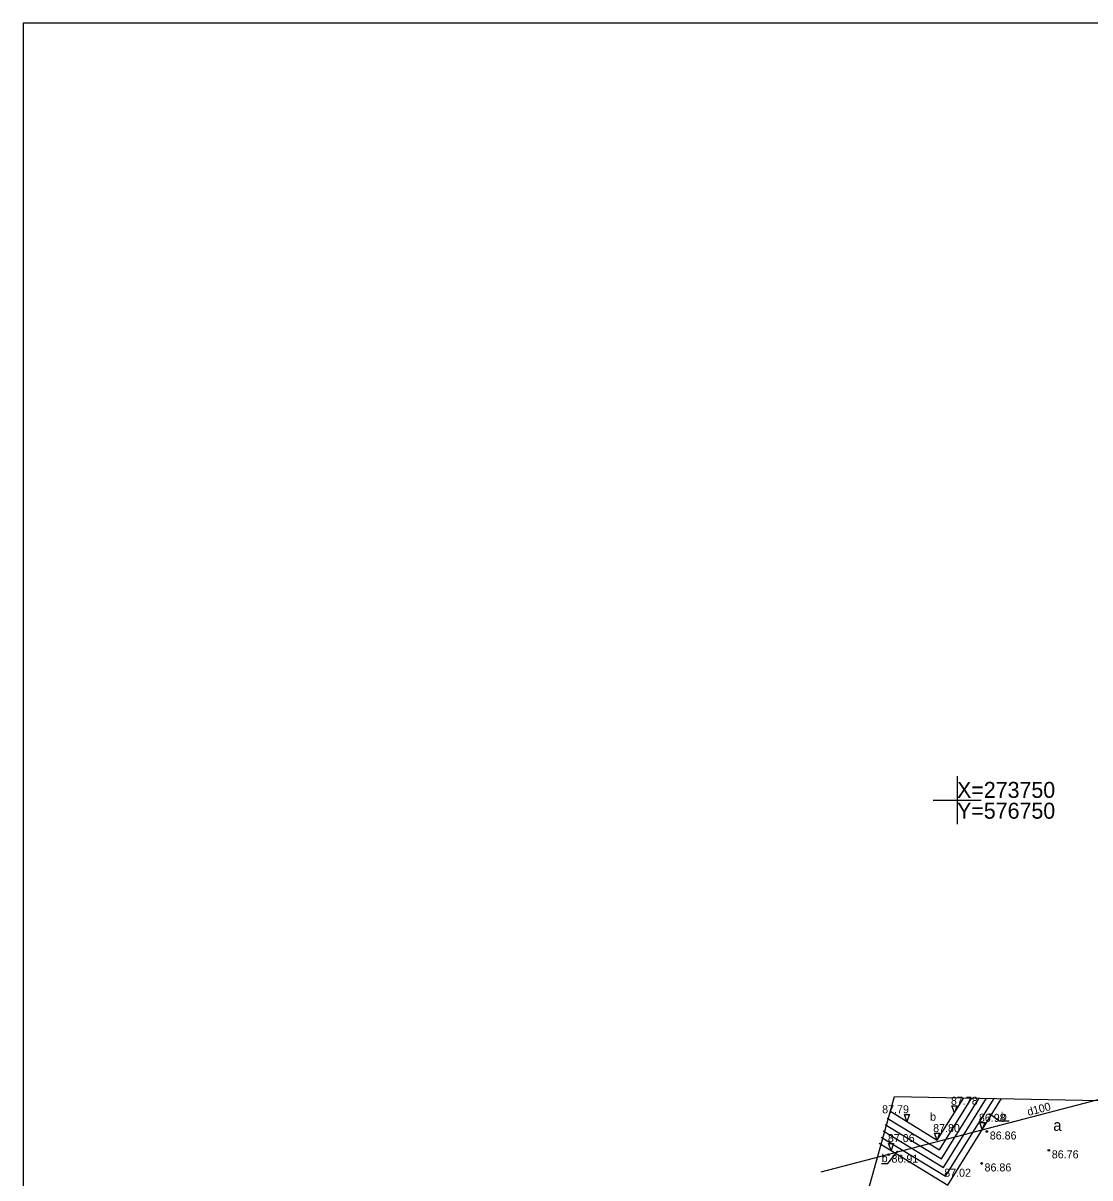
# Model space of a CAD drawing. Extents: x 576692 to 577659, y 273254 to 273799.
# Drawn here: x 576691.6 to 576758.3, y 273726.4 to 273798.6 of the extents above; entities that cross this region are included whole.
import ezdxf

# ---------------------------------------------------------------- set-up
doc = ezdxf.new("R2010")
doc.units = 0
for name, color, linetype in [('APGS_VADP_ZSPR_####_I', 7, 'Continuous'), ('CELI_CMAL_####_####_#', 7, 'Continuous'), ('CELI_TAKA_####_####_#', 7, 'Continuous'), ('CKOM_ELEM_####_####_#', 7, 'Continuous'), ('CKOM_ZEMJ_####_TKST_#', 7, 'Continuous'), ('DREN_ELEM_####_####_#', 7, 'Continuous'), ('HIDT_REZV_####_TKST_#', 7, 'Continuous'), ('RAMI_UZMR_####_####_#', 7, 'Continuous'), ('RELJ_ELEM_####_####_#', 7, 'Continuous'), ('SAKT_ACRL_####_####_#', 7, 'Continuous'), ('SILT_VADP_DREN_TKST_#', 7, 'Continuous')]:
    doc.layers.add(name, color=color, linetype=linetype)

msp = doc.modelspace()

# ---------------------------------------------------------------- linework, layer by layer
at = {"layer": 'APGS_VADP_ZSPR_####_I'}
for p, q in [((576752.625, 273729.943), (576752.027, 273730.414)), ((576753.259, 273729.943), (576752.625, 273729.943)), ((576745.682, 273727.299), (576746.301, 273728.092)), ((576745.267, 273727.299), (576745.682, 273727.299))]:
    msp.add_line(p, q, dxfattribs=at)
at = {"layer": 'CELI_TAKA_####_####_#'}
msp.add_lwpolyline([(576733.342, 273685.822), (576746.079, 273731.492), (576782.392, 273730.79), (576822.461, 273734.186), (576841.308, 273671.168)], dxfattribs=at)
at = {"layer": 'CKOM_ELEM_####_####_#'}
for p, q in [((576750, 273751.5), (576750, 273750)), ((576748.5, 273750), (576750, 273750)), ((576750, 273750), (576750, 273748.5)), ((576750, 273750), (576751.5, 273750))]:
    msp.add_line(p, q, dxfattribs=at)
at = {"layer": 'DREN_ELEM_####_####_#'}
for p, q in [((576748.893, 273728.149), (576750.917, 273731.398)), ((576749.023, 273727.601), (576751.383, 273731.389)), ((576749.153, 273727.053), (576751.848, 273731.38)), ((576749.284, 273726.506), (576752.314, 273731.371)), ((576745.64, 273730.132), (576748.893, 273728.149)), ((576745.388, 273729.349), (576749.153, 273727.053)), ((576745.514, 273729.74), (576749.023, 273727.601)), ((576745.261, 273728.958), (576749.284, 273726.506))]:
    msp.add_line(p, q, dxfattribs=at)
for points in [[(576745.792, 273730.602), (576748.747, 273728.759), (576750.432, 273731.408)], [(576749.414, 273725.958), (576752.779, 273731.362)], [(576745.135, 273728.566), (576749.414, 273725.958)]]:
    msp.add_lwpolyline(points, dxfattribs=at)
at = {"layer": 'RAMI_UZMR_####_####_#'}
msp.add_lwpolyline([(576691.609, 273601.352), (576978.221, 273601.352), (576978.221, 273798.568), (576691.609, 273798.568)], close=True, dxfattribs=at)
at = {"layer": 'RELJ_ELEM_####_####_#'}
for points in [[(576749.682, 273730.898), (576749.982, 273730.898), (576749.832, 273730.465)], [(576746.718, 273730.364), (576747.018, 273730.364), (576746.868, 273729.931)], [(576751.426, 273729.863), (576751.726, 273729.863), (576751.576, 273729.43)], [(576748.597, 273729.192), (576748.897, 273729.192), (576748.747, 273728.759)], [(576745.72, 273728.551), (576746.02, 273728.551), (576745.87, 273728.118)]]:
    msp.add_lwpolyline(points, close=True, dxfattribs=at)
for centre in [(576751.859, 273729.303), (576745.717, 273727.855), (576755.737, 273728.125), (576751.533, 273727.307)]:
    msp.add_circle(centre, 0.05, dxfattribs=at)
at = {"layer": 'SAKT_ACRL_####_####_#'}
msp.add_lwpolyline([(576765.517, 273733.041), (576741.492, 273726.751)], dxfattribs=at)

# ---------------------------------------------------------------- texts
at = {"layer": 'APGS_VADP_ZSPR_####_I'}
for p in [(576748.313, 273729.979), (576752.734, 273730.015), (576745.288, 273727.387)]:
    msp.add_text('b', height=0.5, dxfattribs=at).set_placement(p)
at = {"layer": 'CELI_CMAL_####_####_#'}
msp.add_text('a', height=0.7, dxfattribs=at).set_placement((576756.01, 273729.345))
at = {"layer": 'CKOM_ZEMJ_####_TKST_#'}
for s, p in [('X=273750', (576750, 273750.15)), ('Y=576750', (576750, 273748.85))]:
    msp.add_text(s, height=1, dxfattribs=at).set_placement(p)
at = {"layer": 'HIDT_REZV_####_TKST_#'}
for s, p in [(' 87.79', (576745.131, 273730.441)), (' 87.78', (576749.431, 273730.973)), (' 86.98', (576751.179, 273729.909)), (' 87.80', (576748.317, 273729.265)), (' 87.06', (576745.489, 273728.64)), (' 86.86', (576751.859, 273728.803)), (' 86.76', (576755.737, 273727.625)), (' 86.91', (576745.717, 273727.355)), (' 86.86', (576751.533, 273726.807)), (' 87.02', (576749.01, 273726.475))]:
    msp.add_text(s, height=0.5, dxfattribs=at).set_placement(p)
at = {"layer": 'SILT_VADP_DREN_TKST_#'}
msp.add_text('d100', height=0.5, rotation=14.67333, dxfattribs=at).set_placement((576754.458, 273730.273))

doc.saveas('drawing.dxf')
